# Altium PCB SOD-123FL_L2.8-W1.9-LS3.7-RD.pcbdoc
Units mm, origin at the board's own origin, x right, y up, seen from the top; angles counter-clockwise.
Board outline 17.3 x 14.71 mm, 2 copper layers (Top Layer, Bottom Layer), stack 0 mm thick; 1 components, 0 nets, 2 pads, 0 vias.
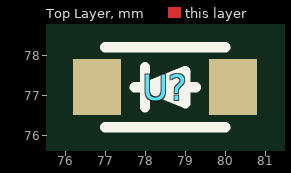
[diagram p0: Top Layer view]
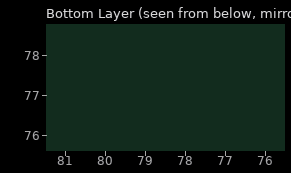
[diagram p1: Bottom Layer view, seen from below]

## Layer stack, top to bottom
Top Layer: signal copper (thickness not stored)
Bottom Layer: signal copper (thickness not stored)

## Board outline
87.15,69.85 69.85,69.85 69.85,84.56 87.15,84.56

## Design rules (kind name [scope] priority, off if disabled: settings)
PasteMaskExpansion "Paste Mask Expansion" [All] p1: expansion=0
SolderMaskExpansion "Solder Mask Expansion" [IsVia] p1: expansion=-25.4 istentingtop=TRUE
SolderMaskExpansion "Solder Mask Expansion" [All] p2: expansion=0.051 istentingtop=FALSE

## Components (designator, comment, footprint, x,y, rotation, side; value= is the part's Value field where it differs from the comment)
U? "" SOD-123FL_L2.8-W1.9-LS3.7-RD 78.5,77.21 r0 top

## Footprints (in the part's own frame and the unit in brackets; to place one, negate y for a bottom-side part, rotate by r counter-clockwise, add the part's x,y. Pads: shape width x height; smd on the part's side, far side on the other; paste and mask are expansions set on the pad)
SOD-123FL_L2.8-W1.9-LS3.7-RD [mm]
  rect 1.2x1.4 smd: 1(-1.7,0) 2(1.7,0)
  silkscreen extent -1.5,-1 1.5,1

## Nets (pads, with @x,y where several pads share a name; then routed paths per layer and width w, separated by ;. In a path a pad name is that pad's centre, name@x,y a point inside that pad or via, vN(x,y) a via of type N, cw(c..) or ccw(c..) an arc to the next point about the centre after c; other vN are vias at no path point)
pads on no net: U?.1 U?.2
